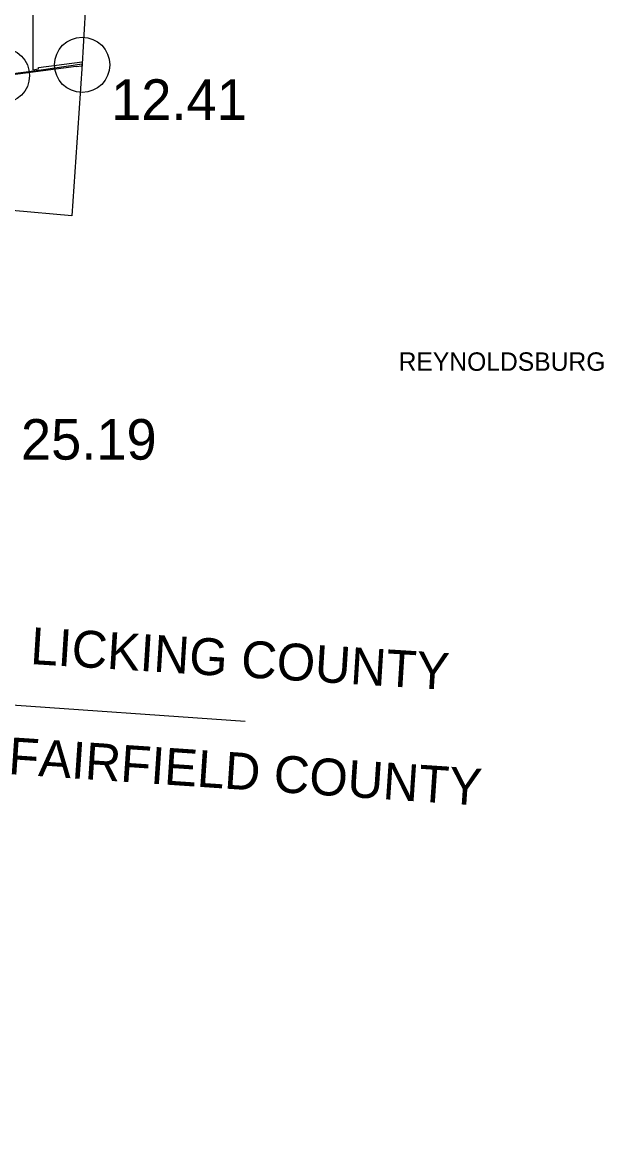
# Model space of a CAD drawing. Extents: x 1729596 to 1934326, y 644115 to 911751.
# Drawn here: x 1890476 to 1906242, y 694653 to 725068 of the extents above; entities that cross this region are included whole.
import ezdxf

# ---------------------------------------------------------------- set-up
doc = ezdxf.new("R2010")
doc.units = 0
for name, color, linetype in [('Default', 7, 'Continuous'), ('GM_X_Adjacent_County', 7, 'Continuous'), ('GM_X_Adjacent_County_Text', 7, 'Continuous'), ('GM_X_Corporation', 7, 'Continuous'), ('GM_X_Corporation_Text', 7, 'Continuous'), ('GM_X_County', 7, 'Continuous'), ('GM_X_State_Route', 7, 'Continuous'), ('GM_X_Township', 7, 'Continuous')]:
    doc.layers.add(name, color=color, linetype=linetype)

msp = doc.modelspace()

# ---------------------------------------------------------------- linework, layer by layer
at = {"layer": 'Default'}
for centre in [(1892097, 723917), (1889918, 723626)]:
    msp.add_circle(centre, 750, dxfattribs=at)
at = {"layer": 'GM_X_Adjacent_County'}
msp.add_line((1889273, 706617), (1896517, 706114), dxfattribs=at)
at = {"layer": 'GM_X_Corporation'}
msp.add_lwpolyline([(1890758, 727769), (1890758, 723783), (1890911, 723805), (1890916, 723842), (1892095, 723998), (1892087, 723879), (1891935, 723861), (1891934, 723876), (1889794, 723593)], dxfattribs=at)
at = {"layer": 'GM_X_County'}
msp.add_lwpolyline([(1892450, 730067), (1892092, 723948), (1892003, 722602), (1891818, 719820), (1890201, 719965), (1890151, 719240), (1889790, 714054), (1889730, 713187), (1889680, 712466), (1889514, 710092), (1889457, 709269), (1889273, 706617), (1886742, 706790), (1881354, 707158), (1881125, 703749), (1880996, 701827), (1880648, 696807), (1880621, 696420), (1881199, 696408), (1881620, 696382), (1884619, 696174), (1885889, 696091), (1885509, 690950)], dxfattribs=at)
at = {"layer": 'GM_X_State_Route'}
msp.add_lwpolyline([(1886877, 723205), (1886929, 723212), (1888789, 723472), (1890221, 723679), (1890925, 723775), (1892092, 723948)], dxfattribs=at)
at = {"layer": 'GM_X_Township'}
msp.add_lwpolyline([(1891818, 719820), (1890201, 719965)], dxfattribs=at)

# ---------------------------------------------------------------- texts
at = {"layer": 'Default'}
for s, p in [('12.41', (1892883, 722425)), ('25.19', (1890436, 713207))]:
    msp.add_text(s, height=1100, dxfattribs=at).set_placement(p)
at = {"layer": 'GM_X_Adjacent_County_Text'}
for s, rotation, p in [('LICKING COUNTY', 356.4293, (1890675, 707664)), ('FAIRFIELD COUNTY', 356.1646, (1890077, 704679))]:
    msp.add_text(s, height=1000, rotation=rotation, dxfattribs=at).set_placement(p)
at = {"layer": 'GM_X_Corporation_Text'}
msp.add_text('REYNOLDSBURG', height=500, rotation=0, dxfattribs=at).set_placement((1900682, 715617))

doc.saveas('drawing.dxf')
